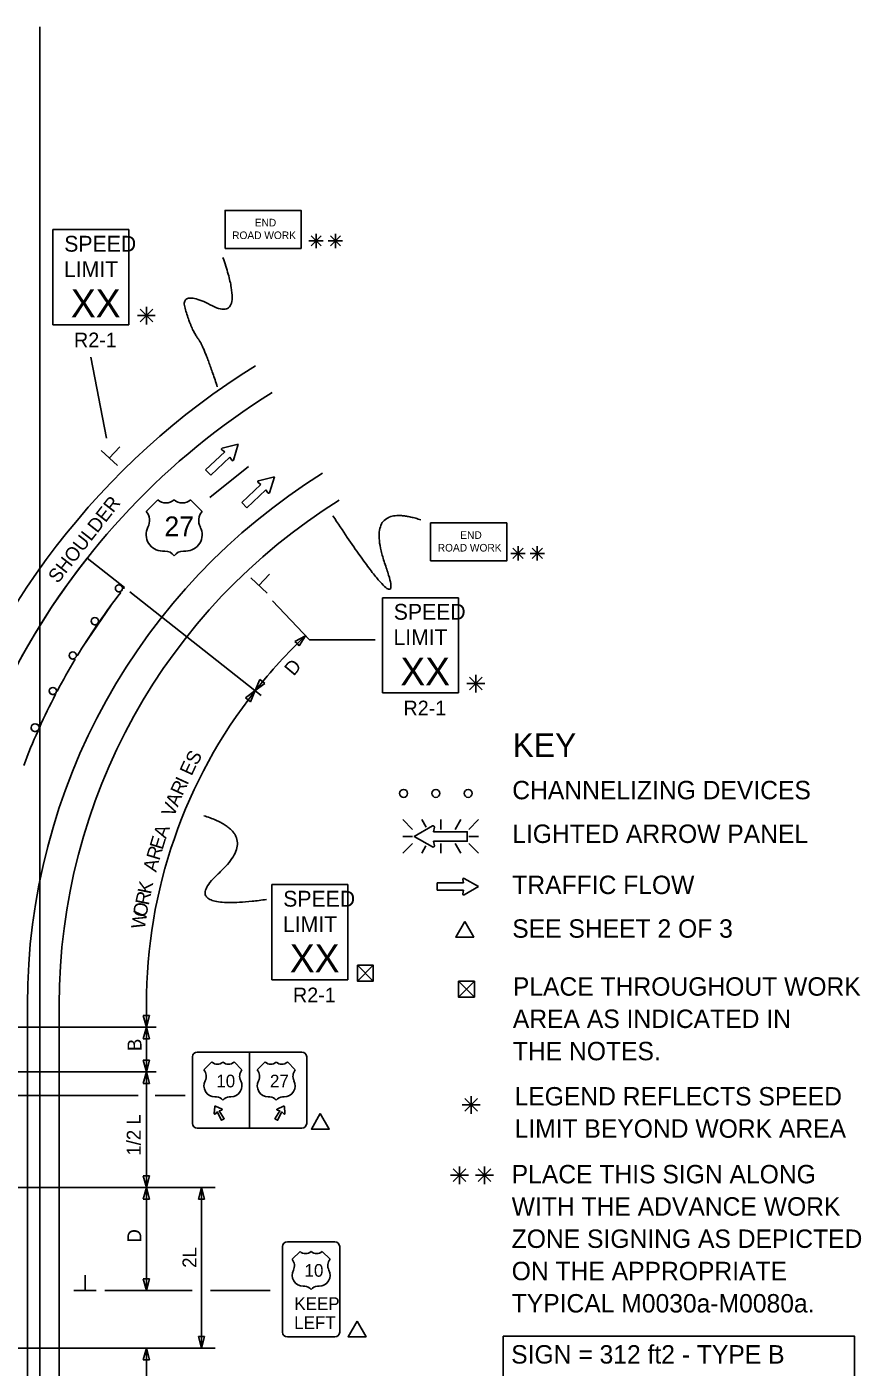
# Model space of a CAD drawing. Extents: x 16512 to 19512, y 5761 to 6974.
# Drawn here: x 16998 to 17419, y 6297 to 6974 of the extents above; entities that cross this region are included whole.
import ezdxf

# ---------------------------------------------------------------- set-up
doc = ezdxf.new("R2010")
doc.units = 0
for name, color, linetype in [('ALI_LEGAL_EX', 7, 'Continuous'), ('MT_SCRATCH_LEVEL_A', 7, 'Continuous'), ('MT_SCRATCH_LEVEL_E', 7, 'Continuous'), ('PAVT_EDGE_EX', 7, 'Continuous'), ('TRAFFIC_SIGNS_PR', 7, 'Continuous'), ('TYPICAL_EX', 7, 'Continuous'), ('TYPICAL_TEXT_DIMEN_EX', 7, 'Continuous'), ('TYPICAL_TEXT_DIMEN_PR', 7, 'Continuous')]:
    doc.layers.add(name, color=color, linetype=linetype)

msp = doc.modelspace()

# ---------------------------------------------------------------- linework, layer by layer
at = {"layer": 'ALI_LEGAL_EX'}
for p, q in [((17004.68, 6974.12), (17004.68, 6155.98)), ((17004.68, 6922.21), (17004.68, 6058.3))]:
    msp.add_line(p, q, dxfattribs=at)
for points in [[(17004.68, 6949.12), (17004.68, 6974.12)], [(17090.52, 6736.48), (17109.97, 6752.18)], [(17026.51, 6661.47), (17040.64, 6682.1)]]:
    msp.add_lwpolyline(points, dxfattribs=at)
at = {"layer": 'MT_SCRATCH_LEVEL_A'}
for points in [[(17047.4, 6690.98), (17028.55, 6705.83)], [(17045.52, 6688.56), (17045.06, 6688.91)], [(17046.41, 6690.77), (17047.26, 6690.79)], [(17033.55, 6672.09), (17033.12, 6672.38)], [(17034.27, 6674.06), (17034.69, 6673.76)], [(17022.59, 6654.94), (17022.2, 6655.17)], [(17023.15, 6656.76), (17023.54, 6656.52)], [(17013.08, 6638.82), (17013.44, 6638.63)], [(17012.67, 6637.16), (17012.32, 6637.35)], [(17003.81, 6618.76), (17003.65, 6618.83)], [(17004.31, 6620.31), (17004.48, 6620.24)]]:
    msp.add_lwpolyline(points, dxfattribs=at)
for centre, radius, start, end in [((17314.45, 6480.53), 364, 141.75977, 180), ((17044.61, 6690.66), 1.8, 3.5129, 180), ((17314.45, 6480.53), 340, 142.2759, 145.36613), ((17044.61, 6690.66), 1.8, 180, 284.5518), ((17314.45, 6480.53), 340, 141.75977, 141.79923), ((17314.45, 6480.53), 340, 145.70741, 148.82754), ((17032.47, 6674.06), 1.8, 0, 180), ((17032.47, 6674.06), 1.8, 180, 291.41483), ((17021.35, 6656.76), 1.8, 0, 180), ((17314.45, 6480.53), 340, 149.13833, 152.28953), ((17021.35, 6656.76), 1.8, 180, 298.27665), ((17011.28, 6638.82), 1.8, 0, 180), ((17011.28, 6638.82), 1.8, 180, 305.13736), ((17314.45, 6480.53), 340, 152.56868, 155.7382), ((17314.45, 6480.53), 340, 156.0121, 159.20322), ((17002.31, 6620.31), 2, 0, 180), ((17002.31, 6620.31), 2, 180, 312.02419)]:
    msp.add_arc(centre, radius, start, end, dxfattribs=at)
at = {"layer": 'MT_SCRATCH_LEVEL_E'}
for p, q in [((17096.59, 6760.6), (17098.04, 6759.51)), ((17104.85, 6763.37), (17096.76, 6761.41)), ((17102.41, 6755.39), (17104.85, 6763.37)), ((17098.04, 6759.51), (17088.37, 6750.45)), ((17090.92, 6747.72), (17100.6, 6756.78)), ((17100.6, 6756.78), (17101.58, 6755.27)), ((17088.37, 6750.45), (17090.92, 6747.72)), ((17123.06, 6746.9), (17114.96, 6744.94)), ((17120.61, 6738.92), (17123.06, 6746.9)), ((17116.24, 6743.04), (17106.57, 6733.98)), ((17109.13, 6731.25), (17118.8, 6740.31)), ((17114.79, 6744.12), (17116.24, 6743.04)), ((17118.8, 6740.31), (17119.78, 6738.8)), ((17106.57, 6733.98), (17109.13, 6731.25)), ((17218.08, 6543.71), (17218.4, 6541.94)), ((17226.01, 6540.09), (17218.77, 6544.2)), ((17218.4, 6541.94), (17205.14, 6541.94)), ((17205.14, 6541.94), (17205.14, 6538.19)), ((17205.14, 6538.19), (17218.4, 6538.19)), ((17218.4, 6538.19), (17218.08, 6536.42)), ((17218.77, 6535.94), (17226.01, 6540.09))]:
    msp.add_line(p, q, dxfattribs=at)
for centre, start, end in [((17096.87, 6760.96), 103.58205, 233.12102), ((17101.96, 6755.54), 213.1934, 342.93033), ((17115.08, 6744.49), 103.58205, 233.12102), ((17120.17, 6739.07), 213.1934, 342.93033), ((17218.54, 6543.79), 60.42484, 189.96381), ((17218.54, 6536.35), 170.03619, 299.77312)]:
    msp.add_arc(centre, 0.463, start, end, dxfattribs=at)
at = {"layer": 'PAVT_EDGE_EX'}
for p, q in [((16998.45, 6480.53), (16998.45, 6125.9)), ((17014.45, 6480.53), (17014.45, 6125.9))]:
    msp.add_line(p, q, dxfattribs=at)
for radius, start, end in [(380, 121.93275, 163.04831), (364, 121.93275, 180), (316, 121.93275, 180), (300, 121.93275, 180), (300, 180, 180.00000277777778)]:
    msp.add_arc((17314.45, 6480.53), radius, start, end, dxfattribs=at)
at = {"layer": 'TRAFFIC_SIGNS_PR'}
for p, q in [((17011.27, 6871.74), (17049.67, 6871.74)), ((17011.27, 6823.74), (17011.27, 6871.74)), ((17049.67, 6823.74), (17049.67, 6871.74)), ((17011.27, 6823.74), (17049.67, 6823.74)), ((17177.5, 6685.93), (17215.9, 6685.93)), ((17177.5, 6637.93), (17177.5, 6685.93)), ((17215.9, 6637.93), (17215.9, 6685.93)), ((17177.5, 6637.93), (17215.9, 6637.93)), ((17187.86, 6573.9), (17192.79, 6568.96)), ((17199.62, 6570.07), (17197.41, 6573.9)), ((17206.94, 6568.96), (17206.94, 6573.9)), ((17214.17, 6568.96), (17217.02, 6573.9)), ((17221.09, 6568.96), (17226.03, 6573.9)), ((17192.79, 6565.41), (17187.86, 6565.41)), ((17221.09, 6565.41), (17226.03, 6565.41)), ((17187.86, 6556.92), (17192.79, 6561.85)), ((17197.37, 6556.92), (17199.48, 6560.58)), ((17206.94, 6561.85), (17206.94, 6556.92)), ((17217.07, 6556.92), (17214.22, 6561.85)), ((17221.09, 6561.85), (17226.03, 6556.91)), ((17121.73, 6541.08), (17160.13, 6541.08)), ((17121.73, 6493.08), (17121.73, 6541.08)), ((17160.13, 6493.08), (17160.13, 6541.08)), ((17121.73, 6493.08), (17160.13, 6493.08)), ((17084.13, 6456.52), (17136.93, 6456.52)), ((17110.53, 6456.52), (17110.53, 6418.12)), ((17081.73, 6454.12), (17081.73, 6420.52)), ((17139.33, 6454.12), (17139.33, 6420.52)), ((17092.71, 6425.47), (17092.99, 6429.09)), ((17093.36, 6429.3), (17096.64, 6427.74)), ((17127.69, 6429.3), (17124.42, 6427.74)), ((17128.35, 6425.47), (17128.07, 6429.09)), ((17084.13, 6418.12), (17136.93, 6418.12)), ((17127.18, 6358.32), (17127.18, 6315.12)), ((17153.58, 6360.72), (17129.58, 6360.72)), ((17155.98, 6315.12), (17155.98, 6358.32)), ((17129.58, 6312.72), (17153.58, 6312.72))]:
    msp.add_line(p, q, dxfattribs=at)
for points in [[(17098.13, 6862.23), (17136.53, 6862.23), (17136.53, 6881.43), (17098.13, 6881.43)], [(17201.84, 6704.49), (17240.24, 6704.49), (17240.24, 6723.69), (17201.84, 6723.69)]]:
    msp.add_lwpolyline(points, close=True, dxfattribs=at)
for points in [[(17202.87, 6570.68), (17193.58, 6565.41), (17202.87, 6560.09)], [(17203.74, 6560.71), (17203.34, 6562.98), (17220.35, 6562.98), (17220.35, 6567.78), (17203.34, 6567.78), (17203.74, 6570.06)], [(17096.6, 6427.25), (17095.19, 6426.86), (17097.71, 6422.88), (17096.38, 6422.12), (17094.19, 6426.29), (17093.15, 6425.26)], [(17124.46, 6427.25), (17125.87, 6426.86), (17123.35, 6422.88), (17124.68, 6422.12), (17126.87, 6426.29), (17127.91, 6425.26)]]:
    msp.add_lwpolyline(points, dxfattribs=at)
for centre, radius in [((17044.61, 6690.66), 1.8), ((17032.47, 6674.06), 1.8), ((17021.35, 6656.76), 1.8), ((17011.28, 6638.82), 1.8), ((17002.31, 6620.31), 2), ((17188.2, 6587.09), 2), ((17204.5, 6587.09), 2), ((17220.8, 6587.09), 2)]:
    msp.add_circle(centre, radius, dxfattribs=at)
for centre, radius, start, end in [((17203.16, 6570.16), 0.598, 350.73078, 118.89165), ((17203.15, 6560.61), 0.597, 241.48329, 9.95933), ((17084.13, 6454.12), 2.4, 90, 180), ((17084.13, 6454.12), 2.4, 90, 180), ((17136.93, 6454.12), 2.4, 0, 90), ((17093.25, 6429.07), 0.26, 64.48226, 175.51774), ((17127.81, 6429.07), 0.26, 4.48226, 115.51774), ((17092.97, 6425.45), 0.26, 175.51775, 314.01151), ((17096.53, 6427.5), 0.26, 285.9885, 64.48226), ((17124.53, 6427.5), 0.26, 115.51774, 254.0115), ((17128.09, 6425.45), 0.26, 225.98849, 4.48225), ((17084.13, 6420.52), 2.4, 180, 270), ((17136.93, 6420.52), 2.4, 270, 0), ((17129.58, 6358.32), 2.4, 90, 180), ((17153.58, 6358.32), 2.4, 0, 90), ((17129.58, 6315.12), 2.4, 180, 270), ((17153.58, 6315.12), 2.4, 270, 0)]:
    msp.add_arc(centre, radius, start, end, dxfattribs=at)
at = {"layer": 'TYPICAL_EX'}
for p, q in [((17058.33, 6729.51), (17064.22, 6735.4)), ((17086.62, 6729.51), (17080.73, 6735.4)), ((17066.57, 6709.45), (17067.75, 6709.45)), ((17078.38, 6709.45), (17077.2, 6709.45)), ((17087.48, 6447.52), (17091.48, 6451.52)), ((17106.68, 6447.52), (17102.68, 6451.52)), ((17114.38, 6447.52), (17118.38, 6451.52)), ((17133.58, 6447.52), (17129.58, 6451.52)), ((17093.07, 6433.91), (17093.87, 6433.91)), ((17101.09, 6433.91), (17100.29, 6433.91)), ((17119.97, 6433.91), (17120.77, 6433.91)), ((17127.99, 6433.91), (17127.19, 6433.91)), ((17131.98, 6351.92), (17135.98, 6355.92)), ((17151.18, 6351.92), (17147.18, 6355.92)), ((17137.57, 6338.31), (17138.37, 6338.31)), ((17145.58, 6338.31), (17144.78, 6338.31))]:
    msp.add_line(p, q, dxfattribs=at)
for centre, radius, start, end in [((17068.35, 6739.69), 5.96, 226.14041, 313.85958), ((17076.6, 6739.69), 5.96, 226.14042, 313.85959), ((17052.74, 6724.78), 7.31, 333.09768, 40.19361), ((17092.21, 6724.78), 7.31, 139.80639, 206.90233), ((17066.59, 6717.69), 8.24, 152.6698, 269.90132), ((17078.36, 6717.69), 8.24, 270.09868, 27.3302), ((17067.77, 6703.54), 5.91, 37.1038, 90.13853), ((17077.19, 6703.54), 5.91, 89.86147, 142.8962), ((17094.28, 6454.43), 4.04, 226.14041, 313.85958), ((17099.88, 6454.43), 4.04, 226.14042, 313.85959), ((17121.18, 6454.43), 4.04, 226.14041, 313.85958), ((17126.78, 6454.43), 4.04, 226.14042, 313.85959), ((17083.69, 6444.31), 4.96, 333.09768, 40.19361), ((17093.08, 6439.5), 5.59, 152.6698, 269.90132), ((17101.08, 6439.5), 5.59, 270.09868, 27.3302), ((17110.47, 6444.31), 4.96, 139.80639, 206.90233), ((17110.59, 6444.31), 4.96, 333.09768, 40.19361), ((17119.98, 6439.5), 5.59, 152.6698, 269.90132), ((17127.97, 6439.5), 5.59, 270.09868, 27.3302), ((17137.37, 6444.31), 4.96, 139.80639, 206.90233), ((17093.88, 6429.9), 4.01, 37.1038, 90.13853), ((17100.28, 6429.9), 4.01, 89.86147, 142.8962), ((17120.78, 6429.9), 4.01, 37.1038, 90.13853), ((17127.17, 6429.9), 4.01, 89.86147, 142.8962), ((17138.78, 6358.83), 4.04, 226.14041, 313.85958), ((17144.38, 6358.83), 4.04, 226.14042, 313.85959), ((17128.19, 6348.71), 4.96, 333.09768, 40.19361), ((17154.97, 6348.71), 4.96, 139.80639, 206.90233), ((17137.58, 6343.9), 5.59, 152.6698, 269.90132), ((17145.57, 6343.9), 5.59, 270.09868, 27.3302), ((17138.38, 6334.3), 4.01, 37.1038, 90.13853), ((17144.77, 6334.3), 4.01, 89.86147, 142.8962)]:
    msp.add_arc(centre, radius, start, end, dxfattribs=at)
at = {"layer": 'TYPICAL_TEXT_DIMEN_EX'}
msp.add_lwpolyline([(17238.46, 6313.09), (17415.73, 6313.09), (17415.73, 6227.77), (17238.46, 6227.77)], close=True, dxfattribs=at)
at = {"layer": 'TYPICAL_TEXT_DIMEN_PR'}
for p, q in [((17141.53, 6868.6), (17146.63, 6863.5)), ((17146.63, 6868.6), (17141.53, 6863.5)), ((17144.08, 6866.05), (17144.08, 6869.62)), ((17151.28, 6868.6), (17156.38, 6863.5)), ((17156.38, 6868.6), (17151.28, 6863.5)), ((17153.83, 6866.05), (17153.83, 6869.62)), ((17144.08, 6866.05), (17140.46, 6866.05)), ((17144.08, 6866.05), (17146.63, 6866.05)), ((17144.08, 6866.05), (17147.66, 6866.05)), ((17144.08, 6866.05), (17144.08, 6862.45)), ((17153.83, 6866.05), (17150.2, 6866.05)), ((17153.83, 6866.05), (17156.38, 6866.05)), ((17153.83, 6866.05), (17157.41, 6866.05)), ((17153.83, 6866.05), (17153.83, 6862.45)), ((17058.46, 6828.35), (17053.93, 6828.35)), ((17061.65, 6831.54), (17055.27, 6825.16)), ((17055.28, 6831.54), (17061.65, 6825.16)), ((17058.46, 6828.35), (17058.46, 6832.81)), ((17058.46, 6828.35), (17061.65, 6828.35)), ((17058.46, 6828.35), (17062.94, 6828.35)), ((17058.46, 6828.35), (17058.46, 6823.85)), ((17038.28, 6766.41), (17030.49, 6807.29)), ((17043.83, 6752.57), (17035.58, 6760.22)), ((17039.7, 6756.39), (17045, 6762.1)), ((17245.95, 6708.31), (17242.32, 6708.31)), ((17243.4, 6710.86), (17248.5, 6705.76)), ((17248.5, 6710.86), (17243.4, 6705.76)), ((17245.95, 6708.31), (17245.95, 6711.87)), ((17245.95, 6708.31), (17248.5, 6708.31)), ((17245.95, 6708.31), (17249.53, 6708.31)), ((17245.95, 6708.31), (17245.95, 6704.71)), ((17255.69, 6708.31), (17252.07, 6708.31)), ((17253.14, 6710.86), (17258.24, 6705.76)), ((17258.24, 6710.86), (17253.14, 6705.76)), ((17255.69, 6708.31), (17255.69, 6711.87)), ((17255.69, 6708.31), (17258.24, 6708.31)), ((17255.69, 6708.31), (17259.28, 6708.31)), ((17255.69, 6708.31), (17255.69, 6704.71)), ((17119.38, 6688.23), (17111.13, 6695.89)), ((17115.25, 6692.06), (17120.55, 6697.77)), ((17050.11, 6688.84), (17116.38, 6636.62)), ((17122.13, 6684.37), (17140.75, 6664.64)), ((17133.42, 6663.86), (17138.77, 6666.74)), ((17138.77, 6666.74), (17135.58, 6661.57)), ((17134.5, 6662.71), (17133.42, 6663.86)), ((17135.58, 6661.57), (17134.5, 6662.71)), ((17140.75, 6664.64), (17173.95, 6664.64)), ((17221.5, 6645.73), (17227.87, 6639.36)), ((17227.87, 6645.73), (17221.5, 6639.36)), ((17224.69, 6642.55), (17224.69, 6647)), ((17108.52, 6635.35), (17113.38, 6638.99)), ((17113.38, 6638.99), (17110.98, 6633.41)), ((17113.38, 6638.99), (17115.77, 6644.56)), ((17118.24, 6642.62), (17113.38, 6638.99)), ((17115.77, 6644.56), (17117.01, 6643.59)), ((17117.01, 6643.59), (17118.24, 6642.62)), ((17224.69, 6642.55), (17220.15, 6642.55)), ((17224.69, 6642.55), (17227.87, 6642.55)), ((17224.69, 6642.55), (17229.16, 6642.55)), ((17224.69, 6642.55), (17224.69, 6638.05)), ((17109.75, 6634.38), (17108.52, 6635.35)), ((17110.98, 6633.41), (17109.75, 6634.38)), ((17004.96, 6621.31), (17003.13, 6622.14)), ((17164.92, 6500.4), (17172.92, 6492.4)), ((17164.92, 6492.4), (17172.92, 6500.4)), ((17215.92, 6492.31), (17223.92, 6484.31)), ((17215.92, 6484.31), (17223.92, 6492.31)), ((17058.45, 6480.53), (17058.45, 6469.09)), ((16977.64, 6469.09), (17063.45, 6469.09)), ((17058.45, 6469.09), (17056.88, 6474.95)), ((17056.88, 6474.95), (17058.45, 6474.95)), ((17056.88, 6463.22), (17058.45, 6469.09)), ((17058.45, 6474.95), (17060.02, 6474.95)), ((17060.02, 6474.95), (17058.45, 6469.09)), ((17058.45, 6469.09), (17058.45, 6446.53)), ((17058.45, 6469.09), (17060.02, 6463.22)), ((17058.45, 6463.22), (17056.88, 6463.22)), ((17060.02, 6463.22), (17058.45, 6463.22)), ((17058.45, 6446.53), (17056.88, 6452.39)), ((17056.88, 6452.39), (17058.45, 6452.39)), ((17058.45, 6452.39), (17060.02, 6452.39)), ((17060.02, 6452.39), (17058.45, 6446.53)), ((16977.64, 6446.53), (17063.45, 6446.53)), ((17056.88, 6440.67), (17058.45, 6446.53)), ((17058.45, 6446.53), (17058.45, 6388.14)), ((17058.45, 6446.53), (17060.02, 6440.67)), ((17058.45, 6440.67), (17056.88, 6440.67)), ((17060.02, 6440.67), (17058.45, 6440.67)), ((17054.35, 6434.68), (16990.46, 6434.68)), ((17062.85, 6434.68), (17078.05, 6434.68)), ((17222.3, 6429.82), (17217.76, 6429.82)), ((17219.11, 6433.01), (17225.48, 6426.64)), ((17225.48, 6433.01), (17219.11, 6426.64)), ((17222.3, 6429.82), (17222.3, 6434.28)), ((17222.3, 6429.82), (17225.48, 6429.82)), ((17222.3, 6429.82), (17226.77, 6429.82)), ((17222.3, 6429.82), (17222.3, 6425.32)), ((17213.28, 6397.51), (17219.66, 6391.13)), ((17219.66, 6397.51), (17213.28, 6391.13)), ((17216.47, 6394.32), (17216.47, 6398.78)), ((17225.84, 6397.51), (17232.21, 6391.13)), ((17232.21, 6397.51), (17225.84, 6391.13)), ((17229.02, 6394.32), (17229.02, 6398.78)), ((17093.24, 6388.14), (16977.64, 6388.14)), ((17058.45, 6388.14), (17056.88, 6394)), ((17056.88, 6394), (17058.45, 6394)), ((17056.88, 6382.28), (17058.45, 6388.14)), ((17058.45, 6394), (17060.02, 6394)), ((17060.02, 6394), (17058.45, 6388.14)), ((17058.45, 6388.14), (17060.02, 6382.28)), ((17058.45, 6388.14), (17058.45, 6336.14)), ((17084.68, 6382.28), (17086.25, 6388.14)), ((17086.25, 6388.14), (17086.25, 6307.03)), ((17086.25, 6388.14), (17087.82, 6382.28)), ((17216.47, 6394.32), (17211.94, 6394.32)), ((17216.47, 6394.32), (17219.66, 6394.32)), ((17216.47, 6394.32), (17220.95, 6394.32)), ((17216.47, 6394.32), (17216.47, 6389.82)), ((17229.02, 6394.32), (17224.49, 6394.32)), ((17229.02, 6394.32), (17232.21, 6394.32)), ((17229.02, 6394.32), (17233.5, 6394.32)), ((17229.02, 6394.32), (17229.02, 6389.82)), ((17058.45, 6382.28), (17056.88, 6382.28)), ((17060.02, 6382.28), (17058.45, 6382.28)), ((17086.25, 6382.28), (17084.68, 6382.28)), ((17087.82, 6382.28), (17086.25, 6382.28)), ((17027.57, 6336.14), (17027.57, 6343.92)), ((17058.45, 6336.14), (17056.88, 6342)), ((17056.88, 6342), (17058.45, 6342)), ((17058.45, 6342), (17060.02, 6342)), ((17060.02, 6342), (17058.45, 6336.14)), ((17033.2, 6336.14), (17021.95, 6336.14)), ((17081.61, 6336.14), (17037.45, 6336.14)), ((17120.94, 6336.14), (17090.76, 6336.14)), ((16953.49, 6307.03), (17093.24, 6307.03)), ((17056.88, 6301.17), (17058.45, 6307.03)), ((17058.45, 6278.47), (17058.45, 6307.03)), ((17058.45, 6307.03), (17060.02, 6301.17)), ((17086.25, 6307.03), (17084.68, 6312.89)), ((17084.68, 6312.89), (17086.25, 6312.89)), ((17086.25, 6312.89), (17087.82, 6312.89)), ((17087.82, 6312.89), (17086.25, 6307.03)), ((17058.45, 6301.17), (17056.88, 6301.17)), ((17060.02, 6301.17), (17058.45, 6301.17))]:
    msp.add_line(p, q, dxfattribs=at)
for points in [[(17219.07, 6522.38), (17214.55, 6514.54), (17223.6, 6514.54)], [(17164.92, 6500.4), (17164.92, 6492.4), (17172.92, 6492.4), (17172.92, 6500.4)], [(17215.92, 6492.31), (17215.92, 6484.31), (17223.92, 6484.31), (17223.92, 6492.31)], [(17146.22, 6425.5), (17141.69, 6417.66), (17150.74, 6417.66)], [(17164.75, 6320.68), (17160.22, 6312.84), (17169.27, 6312.84)]]:
    msp.add_lwpolyline(points, close=True, dxfattribs=at)
for start, end in [(133.33402, 141.75968), (141.75968, 180)]:
    msp.add_arc((17314.45, 6480.53), 256, start, end, dxfattribs=at)
for points in [[(17094.25, 6792.38), (17087.41, 6813.26), (17081.47, 6820.53), (17074.83, 6842.02), (17108.56, 6824.62), (17097.11, 6857.62)], [(17152.53, 6727.28), (17190.76, 6669.11), (17167.55, 6734.81), (17196.9, 6725.23)], [(17087.4, 6575.84), (17116.93, 6566.68), (17073.34, 6527.21), (17119.04, 6533.55)]]:
    msp.add_open_spline(points, degree=2, dxfattribs=at)

# ---------------------------------------------------------------- texts
at = {"layer": 'TRAFFIC_SIGNS_PR'}
for s, height, p in [('END', 3.831, (17113.14, 6873.36)), ('SPEED', 8, (17017.04, 6860.6)), ('ROAD WORK', 3.831, (17101.74, 6866.97)), ('LIMIT', 8, (17016.88, 6847.8)), ('XX', 14.031, (17020.39, 6827.49)), ('R2-1', 7.44, (17021.95, 6812.3)), ('END', 3.831, (17216.84, 6715.61)), ('ROAD WORK', 3.831, (17205.45, 6709.23)), ('SPEED', 8, (17183.26, 6674.79)), ('LIMIT', 8, (17183.1, 6661.99)), ('XX', 14.031, (17186.61, 6641.69)), ('R2-1', 7.44, (17188.17, 6626.49)), ('SPEED', 8, (17127.5, 6529.94)), ('LIMIT', 8, (17127.34, 6517.14)), ('XX', 14.031, (17130.84, 6496.84)), ('R2-1', 7.44, (17132.41, 6481.64)), ('10', 6.4, (17093.74, 6438.72)), ('27', 6.4, (17120.81, 6438.72)), ('10', 6.4, (17138.24, 6343.12)), ('KEEP', 6.4, (17133.12, 6326.32)), ('LEFT', 6.4, (17133.03, 6316.72))]:
    msp.add_text(s, height=height, dxfattribs=at).set_placement(p)
at = {"layer": 'TYPICAL_EX'}
msp.add_text('27', height=10, dxfattribs=at).set_placement((17067.59, 6716.93))
at = {"layer": 'TYPICAL_TEXT_DIMEN_EX'}
for s, height, p in [('KEY', 12, (17243.23, 6605.49)), ('CHANNELIZING DEVICES', 9.3, (17243.04, 6584.15)), ('LIGHTED ARROW PANEL', 9.3, (17243.04, 6562.1)), ('TRAFFIC FLOW', 9.3, (17243.04, 6536.3)), ('SEE SHEET 2 OF 3', 9.3, (17243.04, 6514.25)), ('PLACE THROUGHOUT WORK', 9.3, (17243.35, 6484.99)), ('AREA AS INDICATED IN', 9.3, (17243.35, 6468.69)), ('THE NOTES.', 9.3, (17243.35, 6452.39)), ('LEGEND REFLECTS SPEED', 9.3, (17244.2, 6429.56)), ('LIMIT BEYOND WORK AREA', 9.3, (17244.2, 6413.26)), ('PLACE THIS SIGN ALONG', 9.3, (17242.76, 6390.26)), ('WITH THE ADVANCE WORK', 9.3, (17242.76, 6373.96)), ('ZONE SIGNING AS DEPICTED', 9.3, (17242.76, 6357.66)), ('ON THE APPROPRIATE', 9.3, (17242.76, 6341.36)), ('TYPICAL M0030a-M0080a.', 9.3, (17242.76, 6325.06)), ('SIGN = 312 ft2 - TYPE B', 9.3, (17242.51, 6299.27))]:
    msp.add_text(s, height=height, dxfattribs=at).set_placement(p)
at = {"layer": 'TYPICAL_TEXT_DIMEN_PR'}
for s, rotation, p in [('SHOULDER', 52.01843, (17013.81, 6692.73)), ('D', 50, (17132.79, 6646.01)), ('S', 62.49737, (17083.98, 6600.91)), ('E', 65.17719, (17081.28, 6595.61)), ('R', 65.17719, (17076.62, 6585.54)), ('I', 65.17719, (17079.13, 6590.96)), ('A', 67.85702, (17074.34, 6579.94)), ('V', 67.85702, (17072.25, 6574.78)), ('E', 73.21667, (17066.62, 6558.32)), ('A', 70.53685, (17068.37, 6563.9)), ('R', 73.21667, (17064.99, 6552.92)), ('A', 75.8965, (17063.42, 6547.08)), ('R', 78.57633, (17059.63, 6530.32)), ('K', 78.57633, (17060.77, 6535.95)), ('O', 81.25615, (17058.54, 6524.36)), ('W', 81.25615, (17057.62, 6518.33)), ('B', 90, (17056.01, 6457.04)), ('1/2 L', 90, (17055.59, 6404.27)), ('D', 90, (17055.89, 6360.36)), ('2L', 90, (17083.69, 6347.64))]:
    msp.add_text(s, height=7, rotation=rotation, dxfattribs=at).set_placement(p)

doc.saveas('drawing.dxf')
